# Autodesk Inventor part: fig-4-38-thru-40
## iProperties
Created: 2004-05
Part Number: fig-4-38-thru-40
Document SubType Name: Modeling
Designer: CADCIM Technologies
Manufacturer: Standard
Standards Organization: Custom
Density: 1 g/cm^3
Author: CADCIM Technologies
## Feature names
1. Revolution1
2. Extrusion3
